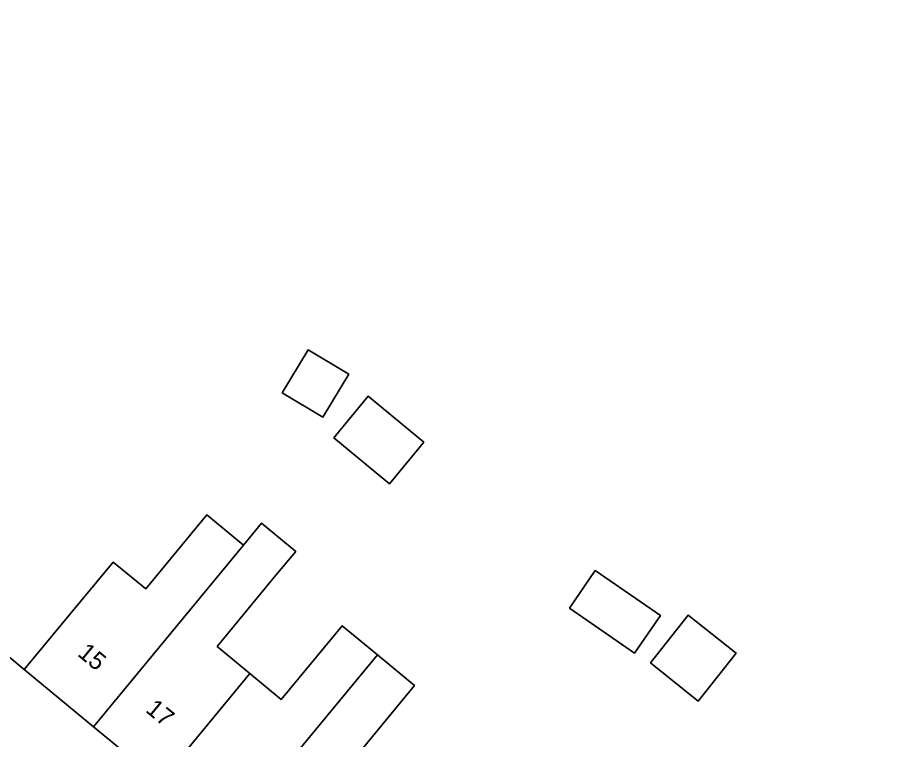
# Model space of a CAD drawing. Extents: x 160157 to 160921, y 381516 to 382045.
# Drawn here: x 160365.48 to 160415.11, y 381924.15 to 381965.07 of the extents above; entities that cross this region are included whole.
import ezdxf

# ---------------------------------------------------------------- set-up
doc = ezdxf.new("R2010")
doc.units = 0
for name, color, linetype in [('IMGEO_Erf', 7, 'Continuous'), ('IMGEO_Pand', 7, 'Continuous'), ('IMGEO_Pand_nummerreeks', 7, 'Continuous'), ('IMGEO_Voetpad_open', 7, 'Continuous')]:
    doc.layers.add(name, color=color, linetype=linetype)

msp = doc.modelspace()

# ---------------------------------------------------------------- linework, layer by layer
at = {"layer": 'IMGEO_Erf'}
for points in [[(160382.809, 381942.414), (160380.501, 381943.791), (160381.959, 381946.235), (160384.267, 381944.858)], [(160388.534, 381940.996), (160386.585, 381938.632), (160383.424, 381941.239), (160385.373, 381943.602)], [(160400.474, 381929.048), (160396.78, 381931.586), (160398.248, 381933.722), (160401.942, 381931.183)], [(160404.089, 381926.331), (160401.374, 381928.486), (160403.52, 381931.19), (160406.235, 381929.034)]]:
    msp.add_lwpolyline(points, close=True, dxfattribs=at)
msp.add_lwpolyline([(160356.601, 381935.838), (160365.87, 381928.117), (160369.053, 381931.974), (160370.91, 381934.192), (160372.759, 381932.692), (160376.219, 381936.884), (160378.296, 381935.169), (160379.322, 381936.412), (160381.261, 381934.812), (160380.235, 381933.569), (160376.809, 381929.418), (160378.657, 381927.893), (160380.442, 381926.42), (160383.893, 381930.601), (160385.894, 381928.949), (160388.004, 381927.207), (160384.559, 381923.033)], dxfattribs=at)
at = {"layer": 'IMGEO_Pand'}
for points in [[(160384.267, 381944.858), (160381.959, 381946.235), (160380.501, 381943.791), (160382.809, 381942.414)], [(160388.534, 381940.996), (160385.373, 381943.602), (160383.424, 381941.239), (160386.585, 381938.632)], [(160369.799, 381924.874), (160378.296, 381935.169), (160376.219, 381936.884), (160372.759, 381932.692), (160370.91, 381934.192), (160369.053, 381931.974), (160365.87, 381928.117)], [(160369.799, 381924.874), (160373.586, 381921.749), (160378.657, 381927.893), (160376.809, 381929.418), (160380.235, 381933.569), (160381.261, 381934.812), (160379.322, 381936.412), (160378.296, 381935.169)], [(160401.942, 381931.183), (160398.248, 381933.722), (160396.78, 381931.586), (160400.474, 381929.048)], [(160406.235, 381929.034), (160403.52, 381931.19), (160401.374, 381928.486), (160404.089, 381926.331)], [(160377.373, 381918.624), (160385.894, 381928.949), (160383.893, 381930.601), (160380.442, 381926.42), (160378.657, 381927.893), (160373.586, 381921.749)], [(160377.373, 381918.624), (160381.302, 381915.381), (160384.485, 381919.238), (160386.378, 381921.531), (160384.559, 381923.033), (160388.004, 381927.207), (160385.894, 381928.949)]]:
    msp.add_lwpolyline(points, close=True, dxfattribs=at)
at = {"layer": 'IMGEO_Voetpad_open'}
msp.add_lwpolyline([(160417.865, 381885.448), (160409.913, 381891.762), (160405.98, 381895.008), (160402.178, 381898.146), (160398.377, 381901.283), (160394.442, 381904.531), (160393.686, 381905.155), (160389.982, 381908.211), (160386.102, 381911.413), (160382.063, 381914.747), (160381.302, 381915.381), (160377.373, 381918.624), (160373.586, 381921.749), (160369.799, 381924.874), (160365.87, 381928.117), (160356.601, 381935.838), (160348.017, 381942.896), (160343.315, 381946.762), (160338.557, 381950.675), (160333.919, 381954.488), (160329.267, 381958.313), (160324.402, 381962.313), (160323.63, 381962.943), (160319.596, 381966.674)], dxfattribs=at)

# ---------------------------------------------------------------- texts
at = {"layer": 'IMGEO_Pand_nummerreeks'}
for s, p in [('15', (160368.836, 381928.937)), ('17', (160372.694, 381925.753))]:
    msp.add_text(s, height=1, rotation=320.4672, dxfattribs=at).set_placement(p)

doc.saveas('drawing.dxf')
